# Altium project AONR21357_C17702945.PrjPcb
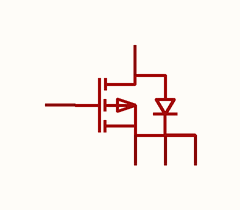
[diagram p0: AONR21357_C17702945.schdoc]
1 sheet, 1 parts. Net scope: global (net labels, ports and power ports of the same name join across sheets).

## Sheet AONR21357_C17702945.schdoc
size 127 x 101 mm

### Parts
Q?  aonr21357_c17702945  [POWERDI3333-8_DMN7022LFGQ-7]  (value not drawn)

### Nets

Not connected (* = marked no-connect by the designer): Q? 1(S) 2(S) 3(S) 4(G) 5(D)

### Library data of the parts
Q? = aonr21357_c17702945: 数量:1个P沟道;漏源电压(Vdss):30V;连续漏极电流(Id):50A;导通电阻(RDS(on)):13mΩ@10V;耗散功率(Pd):37W;阈值电压(Vgs(th)):2.5V;; Manufacturer: MSKSEMI(美森科); AddInBom: yes; ModelId: 296e462280334ba794f41fc0f4558c2c; ModelTransform: 130.708,130.708,0,0,0,0,0,18.625,0; Number: 1个P沟道; Drain to Source Voltage: 30V; Current - Continuous Drain(Id): 50A; Pd - Power Dissipation: 37W; Gate Threshold Voltage (Vgs(th)): 2.5V; Gate Charge(Qg): 22nC@4.5V; Input Capacitance(Ciss): 2.215nF; Reverse Transfer Capacitance (Crss@Vds): 237pF; Type: P沟道; Output Capacitance(Coss): 310pF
